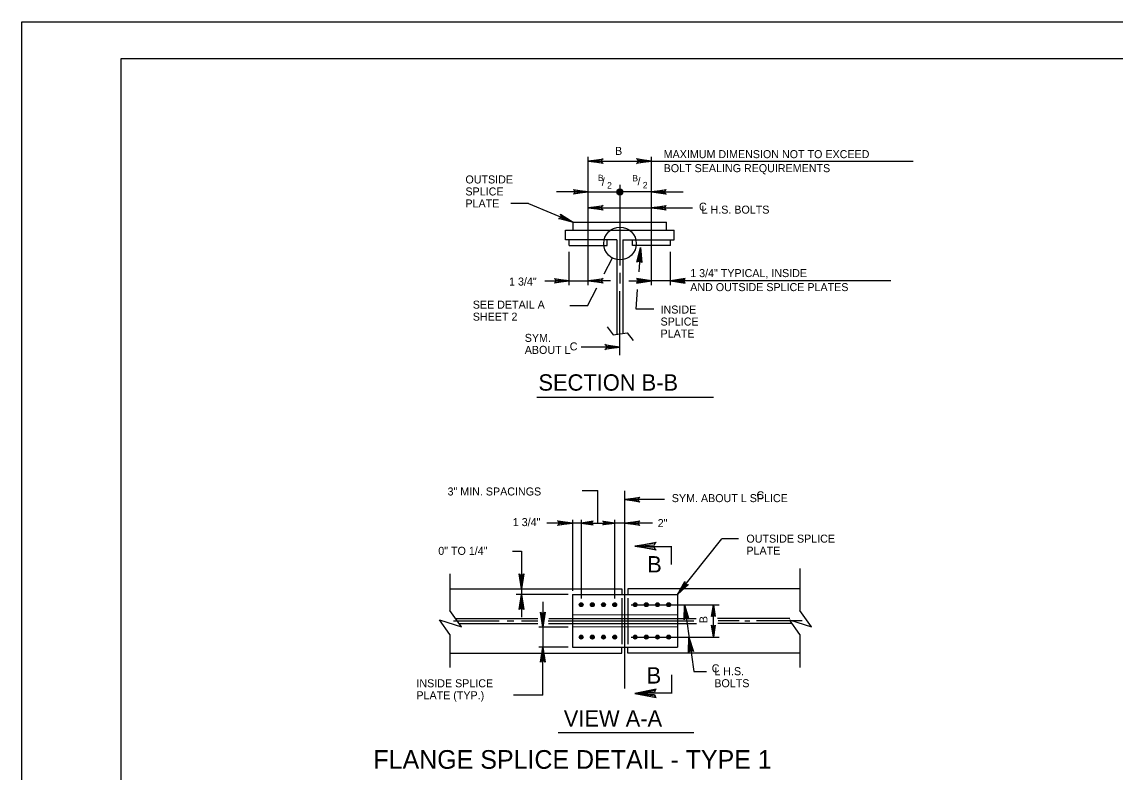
# Model space of a CAD drawing. Extents: x 638466 to 639375, y 297808 to 298996.
# Drawn here: x 638466 to 638908.6, y 298692.8 to 298996.5 of the extents above; entities that cross this region are included whole.
import ezdxf

# ---------------------------------------------------------------- set-up
doc = ezdxf.new("R2010")
doc.units = 0
for name, color, linetype in [('1', 7, 'Continuous'), ('2', 7, 'Continuous'), ('4', 7, 'Continuous'), ('PLT-BNDY', 7, 'Continuous')]:
    doc.layers.add(name, color=color, linetype=linetype)

msp = doc.modelspace()

# ---------------------------------------------------------------- linework, layer by layer
at = {"layer": '1'}
for p, q in [((639291.96, 298981.46), (638505.96, 298981.46)), ((638505.96, 298981.46), (638505.96, 298417.46))]:
    msp.add_line(p, q, dxfattribs=at)
for points in [[(638700.96, 298939.41), (638700.75, 298939.82), (638695.24, 298940.13), (638700.96, 298939.41), (638701.26, 298939.16), (638695.24, 298940.13), (638700.75, 298940.4), (638700.95, 298940.81), (638695.24, 298940.13), (638701.26, 298941.08), (638700.95, 298940.81)], [(638715.12, 298940.84), (638715.33, 298940.43), (638720.84, 298940.13), (638715.12, 298940.84), (638714.82, 298941.1), (638720.84, 298940.13), (638715.33, 298939.85), (638715.13, 298939.44), (638720.84, 298940.13), (638714.82, 298939.17), (638715.13, 298939.44)], [(638689.52, 298928.35), (638689.73, 298927.94), (638695.24, 298927.64), (638689.52, 298928.35), (638689.23, 298928.61), (638695.24, 298927.64), (638689.74, 298927.36), (638689.54, 298926.95), (638695.24, 298927.64), (638689.23, 298926.68), (638689.54, 298926.95)], [(638726.56, 298926.92), (638726.35, 298927.33), (638720.84, 298927.64), (638726.56, 298926.92), (638726.85, 298926.67), (638720.84, 298927.64), (638726.34, 298927.91), (638726.54, 298928.32), (638720.84, 298927.64), (638726.85, 298928.59), (638726.54, 298928.32)], [(638700.96, 298920.51), (638700.75, 298920.93), (638695.24, 298921.23), (638700.96, 298920.51), (638701.26, 298920.26), (638695.24, 298921.23), (638700.75, 298921.5), (638700.95, 298921.91), (638695.24, 298921.23), (638701.26, 298922.19), (638700.95, 298921.91)], [(638726.56, 298920.51), (638726.35, 298920.93), (638720.84, 298921.23), (638726.56, 298920.51), (638726.85, 298920.26), (638720.84, 298921.23), (638726.34, 298921.5), (638726.54, 298921.91), (638720.84, 298921.23), (638726.85, 298922.19), (638726.54, 298921.91)], [(638684.14, 298918.25), (638684.18, 298917.78), (638689.14, 298915.37), (638684.14, 298918.25), (638683.97, 298918.59), (638689.14, 298915.37), (638683.96, 298917.25), (638683.62, 298916.95), (638689.14, 298915.37), (638683.22, 298916.82), (638683.62, 298916.95)], [(638715.26, 298899.46), (638715.68, 298899.64), (638716.36, 298905.12), (638715.26, 298899.46), (638714.99, 298899.19), (638716.36, 298905.12), (638716.26, 298899.61), (638716.65, 298899.38), (638716.36, 298905.12), (638716.91, 298899.06), (638716.65, 298899.38)], [(638681.85, 298892.39), (638682.06, 298891.97), (638687.57, 298891.67), (638681.85, 298892.39), (638681.55, 298892.64), (638687.57, 298891.67), (638682.06, 298891.4), (638681.86, 298890.99), (638687.57, 298891.67), (638681.55, 298890.72), (638681.86, 298890.99)], [(638700.96, 298890.96), (638700.75, 298891.37), (638695.24, 298891.67), (638700.96, 298890.96), (638701.26, 298890.7), (638695.24, 298891.67), (638700.75, 298891.94), (638700.95, 298892.35), (638695.24, 298891.67), (638701.26, 298892.63), (638700.95, 298892.35)], [(638715.12, 298890.96), (638715.33, 298891.37), (638720.84, 298891.67), (638715.12, 298890.96), (638714.83, 298890.7), (638720.84, 298891.67), (638715.34, 298891.94), (638715.13, 298892.35), (638720.84, 298891.67), (638714.83, 298892.63), (638715.13, 298892.35)], [(638734.24, 298892.39), (638734.03, 298891.97), (638728.52, 298891.67), (638734.24, 298892.39), (638734.53, 298892.64), (638728.52, 298891.67), (638734.02, 298891.4), (638734.22, 298890.99), (638728.52, 298891.67), (638734.53, 298890.72), (638734.22, 298890.99)], [(638702.32, 298865.59), (638702.53, 298865.18), (638708.04, 298864.88), (638702.32, 298865.59), (638702.03, 298865.85), (638708.04, 298864.88), (638702.54, 298864.61), (638702.34, 298864.19), (638708.04, 298864.88), (638702.03, 298863.92), (638702.34, 298864.19)], [(638715.82, 298802.41), (638715.61, 298802.82), (638710.1, 298803.13), (638715.82, 298802.41), (638716.12, 298802.16), (638710.1, 298803.13), (638715.61, 298803.4), (638715.81, 298803.81), (638710.1, 298803.13), (638716.12, 298804.08), (638715.81, 298803.81)], [(638683.12, 298794.35), (638683.33, 298793.94), (638688.84, 298793.63), (638683.12, 298794.35), (638682.83, 298794.6), (638688.84, 298793.63), (638683.34, 298793.36), (638683.14, 298792.95), (638688.84, 298793.63), (638682.83, 298792.68), (638683.14, 298792.95)], [(638696.95, 298794.21), (638696.79, 298793.87), (638692.38, 298793.63), (638696.95, 298794.21), (638697.19, 298794.41), (638692.38, 298793.63), (638696.78, 298793.42), (638696.94, 298793.08), (638692.38, 298793.63), (638697.19, 298792.87), (638696.94, 298793.08)], [(638701.39, 298794.21), (638701.56, 298793.87), (638705.97, 298793.63), (638701.39, 298794.21), (638701.16, 298794.41), (638705.97, 298793.63), (638701.56, 298793.42), (638701.4, 298793.08), (638705.97, 298793.63), (638701.16, 298792.87), (638701.4, 298793.08)], [(638715.82, 298792.91), (638715.61, 298793.33), (638710.1, 298793.63), (638715.82, 298792.91), (638716.12, 298792.66), (638710.1, 298793.63), (638715.61, 298793.9), (638715.81, 298794.31), (638710.1, 298793.63), (638716.12, 298794.59), (638715.81, 298794.31)], [(638722.37, 298783.07), (638722.07, 298783.79), (638714.14, 298784.31), (638722.37, 298783.07), (638722.79, 298782.64), (638714.14, 298784.31), (638722.06, 298784.78), (638722.35, 298785.49), (638714.14, 298784.31), (638722.79, 298785.96), (638722.35, 298785.49)], [(638668.96, 298772.75), (638668.55, 298772.54), (638668.25, 298767.03), (638668.96, 298772.75), (638669.22, 298773.05), (638668.25, 298767.03), (638667.98, 298772.54), (638667.57, 298772.74), (638668.25, 298767.03), (638667.29, 298773.05), (638667.57, 298772.74)], [(638735.5, 298768.69), (638735.04, 298768.78), (638731.37, 298764.67), (638735.5, 298768.69), (638735.88, 298768.77), (638731.37, 298764.67), (638734.59, 298769.14), (638734.39, 298769.55), (638731.37, 298764.67), (638734.37, 298769.97), (638734.39, 298769.55)], [(638667.53, 298758.95), (638667.95, 298759.16), (638668.25, 298764.67), (638667.53, 298758.95), (638667.28, 298758.66), (638668.25, 298764.67), (638668.52, 298759.17), (638668.93, 298758.97), (638668.25, 298764.67), (638669.2, 298758.66), (638668.93, 298758.97)], [(638677.6, 298757.25), (638677.19, 298757.04), (638676.88, 298751.53), (638677.6, 298757.25), (638677.85, 298757.54), (638676.88, 298751.53), (638676.61, 298757.03), (638676.2, 298757.23), (638676.88, 298751.53), (638675.93, 298757.54), (638676.2, 298757.23)], [(638734.29, 298754.83), (638734.67, 298755.1), (638734.21, 298760.6), (638734.29, 298754.83), (638734.08, 298754.51), (638734.21, 298760.6), (638735.24, 298755.18), (638735.67, 298755.04), (638734.21, 298760.6), (638735.99, 298754.77), (638735.67, 298755.04)], [(638745.33, 298756.02), (638745.66, 298756.19), (638745.9, 298760.6), (638745.33, 298756.02), (638745.13, 298755.79), (638745.9, 298760.6), (638746.12, 298756.19), (638746.45, 298756.03), (638745.9, 298760.6), (638746.67, 298755.79), (638746.45, 298756.03)], [(638746.48, 298752.06), (638746.15, 298751.89), (638745.9, 298747.48), (638746.48, 298752.06), (638746.68, 298752.29), (638745.9, 298747.48), (638745.68, 298751.89), (638745.36, 298752.05), (638745.9, 298747.48), (638745.14, 298752.29), (638745.36, 298752.05)], [(638736.11, 298741.72), (638736.49, 298741.99), (638736.03, 298747.48), (638736.11, 298741.72), (638735.9, 298741.39), (638736.03, 298747.48), (638737.06, 298742.07), (638737.49, 298741.93), (638736.03, 298747.48), (638737.81, 298741.66), (638737.49, 298741.93)], [(638676.16, 298737.69), (638676.58, 298737.9), (638676.88, 298743.41), (638676.16, 298737.69), (638675.91, 298737.4), (638676.88, 298743.41), (638677.15, 298737.91), (638677.56, 298737.7), (638676.88, 298743.41), (638677.83, 298737.4), (638677.56, 298737.7)], [(638722.37, 298725.97), (638722.07, 298725.26), (638714.14, 298724.73), (638722.37, 298725.97), (638722.79, 298726.4), (638714.14, 298724.73), (638722.06, 298724.26), (638722.35, 298723.56), (638714.14, 298724.73), (638722.79, 298723.08), (638722.35, 298723.56)]]:
    msp.add_lwpolyline(points, dxfattribs=at)
at = {"layer": '2'}
for p, q in [((638708.04, 298930.52), (638708.04, 298897.86)), ((638685.99, 298912.22), (638730.09, 298912.22)), ((638685.99, 298908.29), (638685.99, 298912.22)), ((638689.14, 298915.37), (638726.94, 298915.37)), ((638689.14, 298912.22), (638689.14, 298915.37)), ((638726.94, 298912.22), (638726.94, 298915.37)), ((638730.09, 298908.29), (638730.09, 298912.22)), ((638706.86, 298908.29), (638685.99, 298908.29)), ((638687.57, 298905.92), (638687.57, 298908.29)), ((638702.92, 298905.92), (638702.92, 298908.29)), ((638706.86, 298908.29), (638706.86, 298870.02)), ((638709.22, 298908.29), (638709.22, 298870.39)), ((638709.22, 298908.29), (638730.09, 298908.29)), ((638713.16, 298905.92), (638713.16, 298908.29)), ((638728.52, 298905.92), (638728.52, 298908.29)), ((638687.57, 298905.92), (638702.92, 298905.92)), ((638728.52, 298905.92), (638713.16, 298905.92)), ((638708.04, 298894.9), (638708.04, 298890.52)), ((638708.04, 298861.58), (638708.04, 298887.44)), ((638702.87, 298872.99), (638705.33, 298869.79)), ((638705.33, 298869.79), (638711, 298870.67)), ((638711, 298870.67), (638713.46, 298867.47)), ((638710.1, 298726.64), (638710.1, 298806.74)), ((638780.96, 298775.31), (638780.96, 298758.27)), ((638639.24, 298773.1), (638639.24, 298758.27)), ((638639.24, 298767.03), (638708.92, 298767.03)), ((638708.92, 298767.03), (638708.92, 298764.67)), ((638711.28, 298767.03), (638711.28, 298764.67)), ((638780.96, 298767.03), (638711.28, 298767.03)), ((638688.84, 298764.67), (638688.84, 298743.41)), ((638688.84, 298764.67), (638731.37, 298764.67)), ((638708.92, 298763.28), (638708.92, 298744.61)), ((638711.28, 298763.28), (638711.28, 298744.61)), ((638731.37, 298764.67), (638731.37, 298743.41)), ((638643.96, 298751.62), (638639.24, 298758.27)), ((638785.69, 298751.62), (638780.96, 298758.27)), ((638639.24, 298748.48), (638634.98, 298754.47)), ((638634.98, 298754.47), (638643.96, 298751.62)), ((638640.67, 298754.04), (638659.21, 298754.04)), ((638641.74, 298755.02), (638674.78, 298755.02)), ((638643.13, 298753.06), (638674.78, 298753.06)), ((638662.43, 298754.04), (638665.15, 298754.04)), ((638668.27, 298754.04), (638674.9, 298754.04)), ((638678.99, 298754.04), (638737.97, 298754.04)), ((638679.23, 298753.06), (638739.13, 298753.06)), ((638679.35, 298755.02), (638739.01, 298755.02)), ((638731.36, 298756.42), (638688.84, 298756.56)), ((638776.92, 298755.02), (638747.6, 298755.02)), ((638777.51, 298753.06), (638747.74, 298753.06)), ((638756.35, 298754.04), (638747.81, 298754.04)), ((638758.66, 298754.04), (638760.69, 298754.04)), ((638781.84, 298754.04), (638763.37, 298754.04)), ((638780.96, 298748.48), (638776.71, 298754.47)), ((638776.71, 298754.47), (638785.69, 298751.62)), ((638639.24, 298748.48), (638639.24, 298735.24)), ((638731.36, 298751.66), (638688.84, 298751.53)), ((638780.96, 298748.48), (638780.96, 298735.19)), ((638639.24, 298741.05), (638708.92, 298741.05)), ((638688.84, 298743.41), (638731.37, 298743.41)), ((638708.92, 298741.05), (638708.92, 298743.41)), ((638711.28, 298741.05), (638711.28, 298743.41)), ((638780.96, 298741.05), (638711.28, 298741.05))]:
    msp.add_line(p, q, dxfattribs=at)
for centre, radius in [((638692.39, 298760.6), 0.783), ((638692.39, 298760.6), 0.727), ((638692.39, 298760.6), 0.672), ((638692.39, 298760.6), 0.616), ((638692.39, 298760.6), 0.561), ((638692.39, 298760.6), 0.505), ((638692.39, 298760.6), 0.449), ((638692.39, 298760.6), 0.394), ((638692.39, 298760.6), 0.338), ((638692.39, 298760.6), 0.283), ((638692.39, 298760.6), 0.227), ((638692.39, 298760.6), 0.171), ((638692.39, 298760.6), 0.116), ((638692.39, 298760.6), 0.0601), ((638696.91, 298760.6), 0.783), ((638696.91, 298760.6), 0.727), ((638696.91, 298760.6), 0.672), ((638696.91, 298760.6), 0.616), ((638696.91, 298760.6), 0.561), ((638696.91, 298760.6), 0.505), ((638696.91, 298760.6), 0.449), ((638696.91, 298760.6), 0.394), ((638696.91, 298760.6), 0.338), ((638696.91, 298760.6), 0.283), ((638696.91, 298760.6), 0.227), ((638696.91, 298760.6), 0.171), ((638696.91, 298760.6), 0.116), ((638696.91, 298760.6), 0.0601), ((638701.44, 298760.6), 0.783), ((638701.44, 298760.6), 0.727), ((638701.44, 298760.6), 0.672), ((638701.44, 298760.6), 0.616), ((638701.44, 298760.6), 0.561), ((638701.44, 298760.6), 0.505), ((638701.44, 298760.6), 0.449), ((638701.44, 298760.6), 0.394), ((638701.44, 298760.6), 0.338), ((638701.44, 298760.6), 0.283), ((638701.44, 298760.6), 0.227), ((638701.44, 298760.6), 0.171), ((638701.44, 298760.6), 0.116), ((638701.44, 298760.6), 0.0601), ((638705.97, 298760.6), 0.783), ((638705.97, 298760.6), 0.727), ((638705.97, 298760.6), 0.672), ((638705.97, 298760.6), 0.616), ((638705.97, 298760.6), 0.561), ((638705.97, 298760.6), 0.505), ((638705.97, 298760.6), 0.449), ((638705.97, 298760.6), 0.394), ((638705.97, 298760.6), 0.338), ((638705.97, 298760.6), 0.283), ((638705.97, 298760.6), 0.227), ((638705.97, 298760.6), 0.171), ((638705.97, 298760.6), 0.116), ((638705.97, 298760.6), 0.0601), ((638714.24, 298760.6), 0.783), ((638714.24, 298760.6), 0.727), ((638714.24, 298760.6), 0.672), ((638714.24, 298760.6), 0.616), ((638714.24, 298760.6), 0.561), ((638714.24, 298760.6), 0.505), ((638714.24, 298760.6), 0.449), ((638714.24, 298760.6), 0.394), ((638714.24, 298760.6), 0.338), ((638714.24, 298760.6), 0.283), ((638714.24, 298760.6), 0.227), ((638714.24, 298760.6), 0.171), ((638714.24, 298760.6), 0.116), ((638714.24, 298760.6), 0.0601), ((638718.77, 298760.6), 0.783), ((638718.77, 298760.6), 0.727), ((638718.77, 298760.6), 0.672), ((638718.77, 298760.6), 0.616), ((638718.77, 298760.6), 0.561), ((638718.77, 298760.6), 0.505), ((638718.77, 298760.6), 0.449), ((638718.77, 298760.6), 0.394), ((638718.77, 298760.6), 0.338), ((638718.77, 298760.6), 0.283), ((638718.77, 298760.6), 0.227), ((638718.77, 298760.6), 0.171), ((638718.77, 298760.6), 0.116), ((638718.77, 298760.6), 0.0601), ((638723.3, 298760.6), 0.783), ((638723.3, 298760.6), 0.727), ((638723.3, 298760.6), 0.672), ((638723.3, 298760.6), 0.616), ((638723.3, 298760.6), 0.561), ((638723.3, 298760.6), 0.505), ((638723.3, 298760.6), 0.449), ((638723.3, 298760.6), 0.394), ((638723.3, 298760.6), 0.338), ((638723.3, 298760.6), 0.283), ((638723.3, 298760.6), 0.227), ((638723.3, 298760.6), 0.171), ((638723.3, 298760.6), 0.116), ((638723.3, 298760.6), 0.0601), ((638727.82, 298760.6), 0.783), ((638727.82, 298760.6), 0.727), ((638727.82, 298760.6), 0.672), ((638727.82, 298760.6), 0.616), ((638727.82, 298760.6), 0.561), ((638727.82, 298760.6), 0.505), ((638727.82, 298760.6), 0.449), ((638727.82, 298760.6), 0.394), ((638727.82, 298760.6), 0.338), ((638727.82, 298760.6), 0.283), ((638727.82, 298760.6), 0.227), ((638727.82, 298760.6), 0.171), ((638727.82, 298760.6), 0.116), ((638727.82, 298760.6), 0.0601), ((638692.39, 298747.49), 0.783), ((638692.39, 298747.49), 0.727), ((638692.39, 298747.49), 0.672), ((638692.39, 298747.49), 0.616), ((638692.39, 298747.49), 0.561), ((638692.39, 298747.49), 0.505), ((638692.39, 298747.49), 0.449), ((638692.39, 298747.49), 0.394), ((638692.39, 298747.49), 0.338), ((638692.39, 298747.49), 0.283), ((638692.39, 298747.49), 0.227), ((638692.39, 298747.49), 0.171), ((638692.39, 298747.49), 0.116), ((638692.39, 298747.49), 0.0601), ((638696.91, 298747.49), 0.783), ((638696.91, 298747.49), 0.727), ((638696.91, 298747.49), 0.672), ((638696.91, 298747.49), 0.616), ((638696.91, 298747.49), 0.561), ((638696.91, 298747.49), 0.505), ((638696.91, 298747.49), 0.449), ((638696.91, 298747.49), 0.394), ((638696.91, 298747.49), 0.338), ((638696.91, 298747.49), 0.283), ((638696.91, 298747.49), 0.227), ((638696.91, 298747.49), 0.171), ((638696.91, 298747.49), 0.116), ((638696.91, 298747.49), 0.0601), ((638701.44, 298747.49), 0.783), ((638701.44, 298747.49), 0.727), ((638701.44, 298747.49), 0.672), ((638701.44, 298747.49), 0.616), ((638701.44, 298747.49), 0.561), ((638701.44, 298747.49), 0.505), ((638701.44, 298747.49), 0.449), ((638701.44, 298747.49), 0.394), ((638701.44, 298747.49), 0.338), ((638701.44, 298747.49), 0.283), ((638701.44, 298747.49), 0.227), ((638701.44, 298747.49), 0.171), ((638701.44, 298747.49), 0.116), ((638701.44, 298747.49), 0.0601), ((638705.97, 298747.49), 0.783), ((638705.97, 298747.49), 0.727), ((638705.97, 298747.49), 0.672), ((638705.97, 298747.49), 0.616), ((638705.97, 298747.49), 0.561), ((638705.97, 298747.49), 0.505), ((638705.97, 298747.49), 0.449), ((638705.97, 298747.49), 0.394), ((638705.97, 298747.49), 0.338), ((638705.97, 298747.49), 0.283), ((638705.97, 298747.49), 0.227), ((638705.97, 298747.49), 0.171), ((638705.97, 298747.49), 0.116), ((638705.97, 298747.49), 0.0601), ((638714.24, 298747.49), 0.783), ((638714.24, 298747.49), 0.727), ((638714.24, 298747.49), 0.672), ((638714.24, 298747.49), 0.616), ((638714.24, 298747.49), 0.561), ((638714.24, 298747.49), 0.505), ((638714.24, 298747.49), 0.449), ((638714.24, 298747.49), 0.394), ((638714.24, 298747.49), 0.338), ((638714.24, 298747.49), 0.283), ((638714.24, 298747.49), 0.227), ((638714.24, 298747.49), 0.171), ((638714.24, 298747.49), 0.116), ((638714.24, 298747.49), 0.0601), ((638718.77, 298747.49), 0.783), ((638718.77, 298747.49), 0.727), ((638718.77, 298747.49), 0.672), ((638718.77, 298747.49), 0.616), ((638718.77, 298747.49), 0.561), ((638718.77, 298747.49), 0.505), ((638718.77, 298747.49), 0.449), ((638718.77, 298747.49), 0.394), ((638718.77, 298747.49), 0.338), ((638718.77, 298747.49), 0.283), ((638718.77, 298747.49), 0.227), ((638718.77, 298747.49), 0.171), ((638718.77, 298747.49), 0.116), ((638718.77, 298747.49), 0.0601), ((638723.3, 298747.49), 0.783), ((638723.3, 298747.49), 0.727), ((638723.3, 298747.49), 0.672), ((638723.3, 298747.49), 0.616), ((638723.3, 298747.49), 0.561), ((638723.3, 298747.49), 0.505), ((638723.3, 298747.49), 0.449), ((638723.3, 298747.49), 0.394), ((638723.3, 298747.49), 0.338), ((638723.3, 298747.49), 0.283), ((638723.3, 298747.49), 0.227), ((638723.3, 298747.49), 0.171), ((638723.3, 298747.49), 0.116), ((638723.3, 298747.49), 0.0601), ((638727.82, 298747.49), 0.783), ((638727.82, 298747.49), 0.727), ((638727.82, 298747.49), 0.672), ((638727.82, 298747.49), 0.616), ((638727.82, 298747.49), 0.561), ((638727.82, 298747.49), 0.505), ((638727.82, 298747.49), 0.449), ((638727.82, 298747.49), 0.394), ((638727.82, 298747.49), 0.338), ((638727.82, 298747.49), 0.283), ((638727.82, 298747.49), 0.227), ((638727.82, 298747.49), 0.171), ((638727.82, 298747.49), 0.116), ((638727.82, 298747.49), 0.0601)]:
    msp.add_circle(centre, radius, dxfattribs=at)
at = {"layer": '4'}
for p, q in [((638695.24, 298889.97), (638695.24, 298941.83)), ((638695.24, 298940.13), (638826.76, 298940.13)), ((638720.84, 298889.97), (638720.84, 298941.83)), ((638695.24, 298927.64), (638682.44, 298927.64)), ((638695.24, 298927.64), (638708.04, 298927.64)), ((638720.84, 298927.64), (638708.04, 298927.64)), ((638720.84, 298927.64), (638733.64, 298927.64)), ((638671.09, 298922.94), (638663.87, 298922.94)), ((638671.09, 298922.94), (638689.14, 298915.37)), ((638695.24, 298921.23), (638737.43, 298921.23)), ((638687.57, 298889.97), (638687.57, 298903.36)), ((638716.36, 298905.12), (638715.7, 298895.3)), ((638728.52, 298889.97), (638728.52, 298903.36)), ((638701.74, 298894.53), (638705.06, 298900.92)), ((638677.67, 298891.67), (638687.57, 298891.67)), ((638687.57, 298891.67), (638695.24, 298891.67)), ((638704.33, 298891.67), (638695.24, 298891.67)), ((638711.75, 298891.67), (638720.84, 298891.67)), ((638728.52, 298891.67), (638720.84, 298891.67)), ((638817.7, 298891.67), (638728.52, 298891.67)), ((638695.01, 298881.57), (638698.78, 298888.83)), ((638714.67, 298880.15), (638715.21, 298888.22)), ((638695, 298881.57), (638687.78, 298881.57)), ((638721.84, 298880.15), (638714.67, 298880.15)), ((638708.04, 298864.88), (638692.43, 298864.88)), ((638674.39, 298844.52), (638745.91, 298844.52)), ((638692.8, 298806.82), (638699.17, 298806.82)), ((638699.18, 298793.64), (638699.17, 298806.82)), ((638726.14, 298803.13), (638710.1, 298803.13)), ((638692.38, 298793.63), (638678.5, 298793.63)), ((638688.84, 298794.92), (638688.84, 298766.2)), ((638692.38, 298794.92), (638692.38, 298763.12)), ((638692.38, 298793.63), (638705.97, 298793.63)), ((638705.97, 298763.12), (638705.97, 298794.92)), ((638721.33, 298793.63), (638705.97, 298793.63)), ((638716.41, 298784.17), (638729.12, 298784.17)), ((638728.97, 298776.84), (638728.97, 298784.31)), ((638731.37, 298764.67), (638749.35, 298787.19)), ((638756.04, 298787.19), (638749.35, 298787.19)), ((638664.55, 298782.31), (638668.25, 298782.31)), ((638668.25, 298782.31), (638668.25, 298755.59)), ((638687.11, 298764.67), (638666.1, 298764.67)), ((638676.88, 298761.73), (638676.88, 298751.53)), ((638712.57, 298760.6), (638748.31, 298760.6)), ((638734.21, 298760.6), (638737.97, 298733.55)), ((638745.9, 298747.48), (638745.9, 298760.6)), ((638687.11, 298751.53), (638675.24, 298751.53)), ((638676.88, 298751.53), (638676.88, 298743.41)), ((638712.57, 298747.48), (638748.31, 298747.48)), ((638687.11, 298743.41), (638675.24, 298743.41)), ((638676.88, 298723.97), (638676.88, 298743.41)), ((638728.97, 298732.2), (638728.97, 298724.73)), ((638737.97, 298733.55), (638743.18, 298733.55)), ((638676.88, 298723.97), (638665.01, 298723.97)), ((638716.41, 298724.87), (638729.12, 298724.87)), ((638683.03, 298708.85), (638737.99, 298708.85))]:
    msp.add_line(p, q, dxfattribs=at)
for centre, radius in [((638708.04, 298927.64), 1.24), ((638708.04, 298927.64), 1.15), ((638708.04, 298927.64), 1.06), ((638708.04, 298927.64), 0.974), ((638708.04, 298927.64), 0.886), ((638708.04, 298927.64), 0.798), ((638708.04, 298927.64), 0.71), ((638708.04, 298927.64), 0.622), ((638708.04, 298927.64), 0.534), ((638708.04, 298927.64), 0.446), ((638708.04, 298927.64), 0.359), ((638708.04, 298927.64), 0.271), ((638708.04, 298927.64), 0.183), ((638708.04, 298927.64), 0.0949), ((638708.11, 298906.77), 6.6)]:
    msp.add_circle(centre, radius, dxfattribs=at)
at = {"layer": 'PLT-BNDY'}
msp.add_lwpolyline([(638465.96, 298996.46), (639306.96, 298996.46), (639306.96, 298402.46), (638465.96, 298402.46)], close=True, dxfattribs=at)

# ---------------------------------------------------------------- texts
at = {"layer": '4'}
for s, height, p in [('B', 3.24, (638706.1, 298942.62)), ('MAXIMUM DIMENSION NOT TO EXCEED', 3.24, (638725.79, 298941.31)), ('BOLT SEALING REQUIREMENTS', 3.24, (638725.79, 298935.64)), ('OUTSIDE', 3.24, (638645.54, 298931.07)), ('B', 2.59, (638699.18, 298932)), ('B', 2.59, (638713.1, 298931.91)), ('/', 3.24, (638700.75, 298930.15)), ('2', 2.59, (638702.88, 298929.01)), ('/', 3.24, (638715.21, 298930.29)), ('2', 2.59, (638717.34, 298929.1)), ('SPLICE', 3.24, (638645.54, 298926.21)), ('PLATE', 3.24, (638645.54, 298921.35)), ('C', 3.24, (638740.09, 298920.05)), ('L H.S. BOLTS', 3.2401, (638741.15, 298918.86)), ('1 3/4" TYPICAL, INSIDE', 3.24, (638736.54, 298893.17)), ('1 3/4"', 3.24, (638663.2, 298889.75)), ('AND OUTSIDE SPLICE PLATES', 3.24, (638736.54, 298887.5)), ('SEE DETAIL A', 3.2401, (638648.52, 298880.41)), ('INSIDE', 3.24, (638724.53, 298878.43)), ('SHEET 2', 3.24, (638648.52, 298875.55)), ('SPLICE', 3.24, (638724.53, 298873.57)), ('SYM.', 3.24, (638669.55, 298866.96)), ('PLATE', 3.24, (638724.53, 298868.71)), ('ABOUT L', 3.24, (638669.55, 298862.1)), ('C', 3.24, (638687.77, 298863.51)), ('SECTION B-B', 6.615, (638675.09, 298847.22)), ('3" MIN. SPACINGS', 3.24, (638638.3, 298804.8)), ('C', 3.24, (638763.38, 298803.25)), ('SYM. ABOUT L SPLICE', 3.2401, (638729.09, 298802.11)), ('1 3/4"', 3.24, (638664.7, 298792.4)), ('2"', 3.24, (638723.37, 298792)), ('OUTSIDE SPLICE', 3.2401, (638759.29, 298785.72)), ('0" TO 1/4"', 3.24, (638634.54, 298780.78)), ('PLATE', 3.24, (638759.29, 298780.86)), ('B', 6.61, (638719.12, 298773.64)), ('B', 6.61, (638718.89, 298728.69)), ('C', 3.24, (638745.25, 298733.22)), ('L H.S.', 3.24, (638746.3, 298732.07)), ('INSIDE SPLICE', 3.2401, (638625.69, 298727.18)), ('BOLTS', 3.24, (638746.3, 298727.21)), ('PLATE (TYP.)', 3.2401, (638625.69, 298722.32)), ('VIEW A-A', 6.615, (638685.35, 298711.27)), ('FLANGE SPLICE DETAIL - TYPE 1', 7.56, (638608.29, 298694.2))]:
    msp.add_text(s, height=height, dxfattribs=at).set_placement(p)
msp.add_text('B', height=3.24, rotation=90, dxfattribs=at).set_placement((638743.52, 298753.12))

doc.saveas('drawing.dxf')
